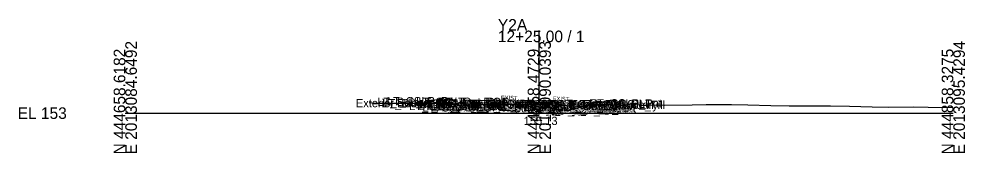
# Model space of a CAD drawing. Extents: x -26 to 203, y -10 to 5517.
# Drawn here: x -25.7 to 202.8, y 4490.3 to 4522.8 of the extents above; entities that cross this region are included whole.
import ezdxf

# ---------------------------------------------------------------- set-up
doc = ezdxf.new("R2010")
doc.units = 0
for name, color, linetype in [('Exist CMT Pavement', 7, 'Continuous'), ('Exist Cross Section Cell', 7, 'Continuous'), ('Exist XS Center Line Elevation Label', 7, 'Continuous'), ('Exist XS Ground Line', 7, 'Continuous'), ('Prop CMT Pvmt Course 1 Wedge', 7, 'Continuous'), ('Prop XS SE Text', 7, 'Continuous'), ('Scratch_Level_0', 7, 'Continuous')]:
    doc.layers.add(name, color=color, linetype=linetype)

msp = doc.modelspace()

# ---------------------------------------------------------------- linework, layer by layer
at = {"layer": 'Exist CMT Pavement'}
msp.add_lwpolyline([(108.94, 4501.72), (108.94, 4501.72)], dxfattribs=at)
at = {"layer": 'Exist Cross Section Cell'}
for p, q in [((100, 4500), (100, 4520)), ((0, 4500), (100, 4500)), ((100, 4500), (200, 4500))]:
    msp.add_line(p, q, dxfattribs=at)
at = {"layer": 'Exist XS Ground Line'}
msp.add_lwpolyline([(58.89, 4502.57), (60.19, 4502.45), (60.9, 4502.44), (70.4, 4502.45), (72.99, 4502.4), (89.7, 4502.13), (90.83, 4502.13), (99.84, 4502.14), (106.66, 4501.83), (109.92, 4501.67), (111.03, 4501.6), (111.5, 4501.57), (111.92, 4502.07), (115.44, 4502.07), (116.92, 4502.07), (124.29, 4501.98), (130.3, 4501.96), (136.92, 4502.02), (140.31, 4502.06), (146.42, 4502.06), (150.33, 4502.02), (155.92, 4501.87), (160.34, 4501.75), (165.43, 4501.78), (170.36, 4501.75), (174.93, 4501.7), (180.38, 4501.55), (184.43, 4501.48), (190.39, 4501.5), (193.94, 4501.45), (200, 4501.38)], dxfattribs=at)
at = {"layer": 'Prop CMT Pvmt Course 1 Wedge'}
msp.add_lwpolyline([(108.94, 4501.74), (108.94, 4501.74)], dxfattribs=at)

# ---------------------------------------------------------------- texts
at = {"layer": 'Exist Cross Section Cell'}
for s, p in [('Y2A', (90, 4520)), ('12+25.00 / 1', (90, 4517.2)), ('EL 153', (-26, 4498.6))]:
    msp.add_text(s, height=2.8, dxfattribs=at).set_placement(p)
for s, p in [('E 2013084.6492', (2.8, 4490)), ('E 2013090.0393', (102.8, 4490)), ('E 2013095.4294', (202.8, 4490)), ('N 444658.6182', (0, 4490)), ('N 444758.4729', (100, 4490)), ('N 444858.3275', (200, 4490))]:
    msp.add_text(s, height=2.8, rotation=90, dxfattribs=at).set_placement(p)
at = {"layer": 'Exist XS Center Line Elevation Label'}
msp.add_text('155.13', height=2, dxfattribs=at).set_placement((96.23, 4497.13))
at = {"layer": 'Prop XS SE Text'}
for rotation, p in [(359.4271, (90.74, 4503.22)), (358.2816, (103.23, 4503.03))]:
    msp.add_text('EXIST.', height=1, rotation=rotation, dxfattribs=at).set_placement(p)
at = {"layer": 'Scratch_Level_0'}
for s, p in [('Exterior Boundary', (55.69, 4501.43)), ('LT_Sub_Trench_Out_DLT', (60.87, 4501.76)), ('LT_Slope_Fill', (62.06, 4501.43)), ('LT_CSLP_Pnt', (63.17, 4501.91)), ('LT_CG1_Shelf_Out', (68.55, 4500.73)), ('LT_CG_Top_Face', (70.26, 4501.72)), ('LT_CG_Top_BOC', (70.78, 4501.72)), ('LT_CG_Bot_BOC', (70.81, 4500.72)), ('LT_PV_Sub_Tie_Out', (70.96, 4501.19)), ('LT_CG_Top_Gut', (71.24, 4501.22)), ('LT_Sub_OEOP', (71.78, 4500.4)), ('LT_PV_OEEOP_EG', (73.54, 4501.19)), ('LT_CG_Bot_IE', (74.91, 4500.7)), ('LT_Sub_OEOT', (75.08, 4500.36)), ('LT_PV2_OEOT', (75.17, 4501.03)), ('LT_PV3_OEOT', (75.17, 4500.7)), ('LT_Sub_OEEOP', (75.21, 4500.35)), ('LT_PV2_OEEOP', (75.31, 4501.02)), ('LT_PV3_OEEOP', (75.31, 4500.69)), ('LT_PV1_OEOT', (75.74, 4501.28)), ('LT_PV1_OEEOP', (75.87, 4501.15)), ('LT_PV_IEEOP_EG', (88.19, 4501.13)), ('LT_PV2_IEEOP', (89.95, 4500.88)), ('LT_PV3_IEEOP', (89.95, 4500.55)), ('LT_PV1_IEEOP', (90.52, 4501.01)), ('Sub_PGL', (93.81, 4500.21)), ('RT_PV_Sub_Tie_Out', (93.82, 4500.72)), ('PV2_PGL', (93.91, 4500.88)), ('PV3_PGL', (93.91, 4500.55)), ('PV1_PGL', (94.47, 4501.13)), ('RT_Sub_Trench_Out_DLT', (95.22, 4501.24)), ('RT_PV_Sub_Tie_In', (95.47, 4500.71)), ('RT_PV_OEEOP_EG', (96.43, 4500.72)), ('RT_PV_IEEOP_EG', (97.08, 4500.72)), ('RT_PV2_OEEOP', (98.2, 4500.61)), ('RT_PV3_OEEOP', (98.2, 4500.28)), ('RT_PV1_OEEOP', (98.76, 4500.74)), ('RT_PV2_IEEOP', (98.84, 4500.61)), ('RT_PV3_IEEOP', (98.84, 4500.28)), ('RT_CG_Top_Face', (99.15, 4501.19)), ('RT_PV1_IEEOP', (99.41, 4500.74)), ('RT_CG1_Shelf_Out', (99.44, 4500.16)), ('RT_CG_Bot_IE', (99.8, 4500.25)), ('RT_PV2_OEOT', (100.06, 4500.58)), ('RT_PV3_OEOT', (100.06, 4500.25)), ('RT_CG_Top_Gut', (100.12, 4500.69)), ('RT_PV1_OEOT', (100.63, 4500.83)), ('RT_CG_Top_BOC', (100.67, 4501.19)), ('RT_CG_Bot_BOC', (100.7, 4500.17)), ('Exterior Boundary', (107.25, 4500.99)), ('RT_CSLP_Pnt', (112.06, 4501.38)), ('RT_Slope_Fill', (113.58, 4500.99)), ('RT_Sub_OEEOP', (98.1, 4499.95)), ('RT_Sub_IEEOP', (98.75, 4499.95)), ('RT_Sub_OEOT', (99.97, 4499.92)), ('RT_Sub_OEOP', (103.34, 4499.82))]:
    msp.add_text(s, height=2, dxfattribs=at).set_placement(p)

doc.saveas('drawing.dxf')
